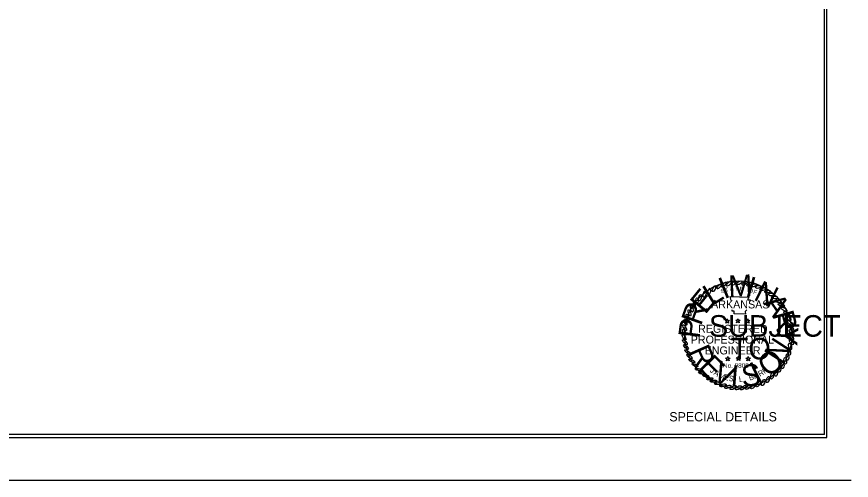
# Model space of a CAD drawing. Extents: x 714919 to 718439, y 1619644 to 1621844.
# Drawn here: x 717000 to 718439, y 1619644 to 1620443 of the extents above; entities that cross this region are included whole.
import ezdxf

# ---------------------------------------------------------------- set-up
doc = ezdxf.new("R2010")
doc.units = 0
for name, color, linetype in [('R_Border', 7, 'Continuous'), ('R_Border Notes', 7, 'Continuous'), ('R_Border PE', 7, 'Continuous'), ('R_Border Prem', 7, 'Continuous'), ('R_No Plot', 7, 'Continuous')]:
    doc.layers.add(name, color=color, linetype=linetype)

msp = doc.modelspace()

# ---------------------------------------------------------------- linework, layer by layer
at = {"layer": 'R_Border'}
for p, q in [((718393, 1619722.6), (718392.9, 1621777.2)), ((718393, 1619722.6), (715231, 1619722.6)), ((714918.9, 1619643.7), (718439.1, 1619643.9))]:
    msp.add_line(p, q, dxfattribs=at)
at = {"layer": 'R_Border PE'}
for points in [[(718232, 1619953.9), (718229.9, 1619960.4), (718262.5, 1619959.5), (718260.1, 1619955.1), (718265.1, 1619954.8), (718264.8, 1619954.2)], [(718258.6, 1619937.6), (718255.9, 1619934.7), (718256.5, 1619930.2), (718237, 1619930.8), (718237, 1619935), (718233.5, 1619935), (718233.5, 1619937.6)]]:
    msp.add_lwpolyline(points, dxfattribs=at)
for points in [[(718225.2, 1619921.9), (718226.1, 1619919), (718229, 1619919), (718226.6, 1619917.5), (718227.5, 1619914.5), (718225.2, 1619916.3), (718222.8, 1619914.5), (718223.7, 1619917.5), (718221.3, 1619919), (718224.3, 1619919)], [(718243.5, 1619922.2), (718244.4, 1619919.6), (718247.1, 1619919.6), (718245, 1619917.8), (718245.9, 1619915.1), (718243.5, 1619916.6), (718241.1, 1619915.1), (718242, 1619917.8), (718239.7, 1619919.6), (718242.6, 1619919.6)], [(718260.4, 1619921.9), (718261.3, 1619919), (718264.2, 1619919), (718261.9, 1619917.5), (718262.8, 1619914.5), (718260.4, 1619916.3), (718258, 1619914.5), (718258.9, 1619917.5), (718256.5, 1619919), (718259.5, 1619919)], [(718226.1, 1619857.1), (718226.9, 1619854.1), (718229.9, 1619854.1), (718227.5, 1619852.7), (718228.4, 1619849.7), (718226.1, 1619851.5), (718223.7, 1619849.7), (718224.6, 1619852.7), (718222.2, 1619854.1), (718225.2, 1619854.1)], [(718244.4, 1619857.4), (718245.3, 1619854.7), (718248, 1619854.7), (718245.6, 1619853), (718246.8, 1619850.3), (718244.4, 1619851.8), (718242, 1619850.3), (718242.9, 1619853), (718240.6, 1619854.7), (718243.5, 1619854.7)], [(718261.3, 1619857.1), (718262.2, 1619854.1), (718265.1, 1619854.1), (718262.8, 1619852.7), (718263.6, 1619849.7), (718261.3, 1619851.5), (718258.9, 1619849.7), (718259.8, 1619852.7), (718257.4, 1619854.1), (718260.4, 1619854.1)]]:
    msp.add_lwpolyline(points, close=True, dxfattribs=at)
for centre, major_axis, ratio in [((718211.3, 1619978.1), (-3.58, -4.44), 0.329518), ((718219.4, 1619981), (-3.64, -4.4), 0.329518), ((718228.2, 1619982.8), (-4.59, -4.21), 0.348728), ((718236.5, 1619983.3), (-3.87, -3.02), 0.44237), ((718246.2, 1619984.2), (-4.21, -2.45), 0.475469), ((718254.9, 1619983.3), (-4.21, -2.45), 0.475469), ((718263, 1619981.8), (-4.21, -2.45), 0.475469), ((718271, 1619979.8), (-4.64, -1.48), 0.475469), ((718186, 1619964.7), (-1.53, -5.49), 0.394697), ((718193.9, 1619969.2), (-1.53, -5.49), 0.375751), ((718202.3, 1619974.1), (-2.46, -5.15), 0.329518), ((718278.4, 1619977), (-4.79, -0.89), 0.475469), ((718286.3, 1619973.4), (-4.85, -0.42), 0.475469), ((718294.6, 1619969.1), (-4.85, -0.42), 0.475469), ((718301.2, 1619964), (-4.87, 0.11), 0.475469), ((718168.2, 1619946.3), (0, -5.7), 0.322879), ((718172.9, 1619952.3), (0, -5.7), 0.322879), ((718178.1, 1619958.4), (-1.53, -5.49), 0.391724), ((718306.8, 1619958.7), (-5.09, 0.7), 0.451028), ((718313.1, 1619952.3), (-5.17, 1.18), 0.436264), ((718160, 1619932.4), (1.57, -5.48), 0.322879), ((718163.8, 1619939.1), (1.57, -5.48), 0.322879), ((718318.3, 1619946), (-5.3, 1.59), 0.418512), ((718322.6, 1619938.8), (-4.99, 2.77), 0.40589), ((718156.5, 1619924.5), (1.57, -5.48), 0.322879), ((718327.6, 1619930.9), (-4.66, 3.28), 0.40589), ((718330.7, 1619922.9), (-4.3, 3.75), 0.40589), ((718151.7, 1619907), (3.04, -4.83), 0.322879), ((718153.3, 1619916.4), (1.57, -5.48), 0.322879), ((718333.3, 1619915), (-4.3, 3.75), 0.40589), ((718335, 1619907.4), (-4.1, 3.96), 0.40589), ((718150.7, 1619890.5), (3.04, -4.83), 0.322879), ((718151.2, 1619898.9), (3.04, -4.83), 0.322879), ((718335.9, 1619899), (-3.5, 4.5), 0.40589), ((718336.1, 1619890.8), (-2.77, 4.99), 0.40589), ((718152.1, 1619881.8), (3.92, -4.14), 0.322879), ((718333.5, 1619874.4), (-1.48, 5.51), 0.40589), ((718335.6, 1619882.2), (-2.3, 5.22), 0.40589), ((718154, 1619873.5), (3.92, -4.14), 0.322879), ((718156.5, 1619864.7), (4.29, -3.76), 0.322879), ((718331.7, 1619864.9), (-1.02, 5.61), 0.40589), ((718159.9, 1619857.1), (4.67, -3.27), 0.322879), ((718164.1, 1619849.5), (5.13, -2.49), 0.322879), ((718325.2, 1619849.5), (-0.33, 5.69), 0.40589), ((718329, 1619856.3), (-0.33, 5.69), 0.40589), ((718169.4, 1619842.2), (5.13, -2.49), 0.322879), ((718175.4, 1619834.5), (5.58, -1.19), 0.322879), ((718315, 1619835.7), (0.91, 5.63), 0.40589), ((718320.7, 1619841.9), (0.27, 5.7), 0.40589), ((718181.1, 1619828.7), (5.58, -1.19), 0.322879), ((718188.1, 1619823.7), (5.58, -1.19), 0.322879), ((718295.2, 1619817.4), (2.26, 5.24), 0.40589), ((718302.6, 1619823.8), (1.36, 5.54), 0.40589), ((718309.5, 1619828.7), (0.91, 5.63), 0.40589), ((718194.9, 1619818.6), (5.68, 0.48), 0.322879), ((718201.6, 1619814.7), (5.68, 0.48), 0.322879), ((718208.8, 1619810.9), (5.68, 0.48), 0.40589), ((718217.8, 1619807.4), (5.5, 1.52), 0.40589), ((718226.1, 1619804.8), (5.5, 1.52), 0.40589), ((718235.3, 1619803.4), (4.91, 2.91), 0.40589), ((718252.6, 1619803.2), (4.63, 3.33), 0.40589), ((718261.7, 1619804.5), (4.36, 3.68), 0.40589), ((718270.1, 1619805.8), (4.08, 3.98), 0.40589), ((718278.8, 1619809.6), (3.39, 4.59), 0.40589), ((718287.2, 1619812.3), (2.43, 5.16), 0.40589), ((718244.5, 1619803.3), (4.91, 2.91), 0.40589)]:
    msp.add_ellipse(centre, major_axis=major_axis, ratio=ratio, dxfattribs=at)
at = {"layer": 'R_Border Prem'}
msp.add_circle((718244.3, 1619895), 92.6, dxfattribs=at)
at = {"layer": 'R_No Plot'}
msp.add_lwpolyline([(715227, 1619717.4), (718396.9, 1619717.5), (718397, 1621782.6), (715226.9, 1621782.4)], close=True, dxfattribs=at)

# ---------------------------------------------------------------- texts
at = {"layer": 'R_Border Notes'}
msp.add_text('SPECIAL DETAILS', height=16, rotation=359.9984, dxfattribs=at).set_placement((718125.2, 1619745.2))
at = {"layer": 'R_Border PE'}
for s, height, rotation, p in [('S', 6.91, 19.5814, (718215.1, 1619965.7)), ('T', 6.91, 14.9614, (718222.5, 1619968.1)), ('A', 6.91, 5.7216, (718229.9, 1619969.9)), ('T', 6.91, 1.1017, (718238.2, 1619970.5)), ('E', 6.91, 356.4818, (718246.2, 1619970.5)), ('O', 6.91, 342.6221, (718261.6, 1619968.4)), ('F', 6.91, 338.0022, (718269.3, 1619966)), ('ARKANSAS', 13.81, 360, (718197.3, 1619940)), ('REGISTERED', 13.81, 360, (718174.8, 1619898)), ('PROFESSIONAL', 13.814, 360, (718162.1, 1619879.3)), ('ENGINEER', 13.81, 360, (718186.1, 1619860.7)), ('J', 9.6, 322.4167, (718194.3, 1619831.3)), ('No. 9808', 7.89, 360, (718217.9, 1619837.6)), ('R', 9.6, 35.2219, (718289.4, 1619826.9)), ('A', 9.6, 328.0171, (718200.8, 1619826.5)), ('M', 9.6, 333.6175, (718209.1, 1619821.7)), ('E', 9.6, 344.8183, (718218.6, 1619817.6)), ('S', 9.6, 350.4187, (718227, 1619815.2)), ('L', 9.6, 1.6195, (718245.3, 1619813.3)), ('B', 9.6, 18.4207, (718263.9, 1619815.4)), ('A', 9.6, 24.0211, (718272.7, 1619818.1)), ('R', 9.6, 29.6215, (718281.5, 1619822.1)), ('.', 9.6, 7.2199, (718254.2, 1619813.9))]:
    msp.add_text(s, height=height, rotation=rotation, dxfattribs=at).set_placement(p)
at = {"layer": 'R_Border Prem'}
for s, height, rotation, p in [('M', 37.2, 2.6943, (718227.8, 1619959.7)), ('I', 37.2, 343.3781, (718254.1, 1619960.3)), ('I', 37.2, 22.0105, (718219.7, 1619955.6)), ('N', 37.2, 333.7199, (718268.7, 1619955.8)), ('E', 37.2, 50.9849, (718187.1, 1619928.4)), ('L', 37.2, 31.6686, (718198.1, 1619943.4)), ('A', 37.2, 304.7456, (718286.2, 1619949.2)), ('R', 37.2, 70.3011, (718179.7, 1619908.8)), ('SUBJECT', 37.24, 360, (718193.6, 1619891.2)), ('R', 37.2, 285.4294, (718302.3, 1619930.4)), ('P', 37.2, 82.6089, (718177.2, 1619887.1)), ('Y', 37.2, 266.1131, (718310.9, 1619910.4)), ('TO', 37.24, 360, (718231.2, 1619852.1)), ('N', 37.2, 57.1378, (718317.9, 1619842.5)), ('R', 37.2, 293.7639, (718157.9, 1619866.8)), ('O', 37.2, 36.5754, (718295.2, 1619820.3)), ('E', 37.2, 314.3262, (718173.9, 1619837.6)), ('V', 37.2, 334.8885, (718197, 1619817.3)), ('I', 37.2, 355.4508, (718229.8, 1619805.5)), ('S', 37.2, 5.732, (718251.3, 1619804.9)), ('I', 37.2, 26.2943, (718276.3, 1619810))]:
    msp.add_text(s, height=height, rotation=rotation, dxfattribs=at).set_placement(p)

doc.saveas('drawing.dxf')
